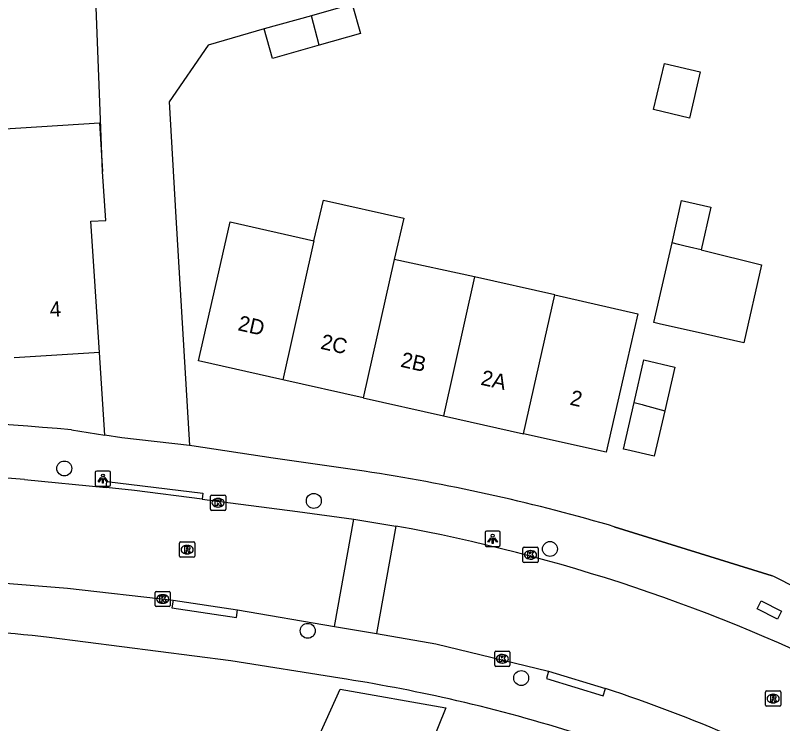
# Model space of a CAD drawing. Extents: x 163010 to 163853, y 382793 to 383982.
# Drawn here: x 163356.6 to 163406.8, y 383532.5 to 383579 of the extents above; entities that cross this region are included whole.
import ezdxf

# ---------------------------------------------------------------- set-up
doc = ezdxf.new("R2010")
doc.units = 0
for name, color, linetype in [('IMGEO_Boom', 7, 'Continuous'), ('IMGEO_Kolk', 7, 'Continuous'), ('IMGEO_Lichtpunt', 7, 'Continuous'), ('IMGEO_Muur', 7, 'Continuous'), ('IMGEO_Pand', 7, 'Continuous'), ('IMGEO_Pand_nummerreeks', 7, 'Continuous'), ('IMGEO_Rijbaan_lokaal_open', 7, 'Continuous'), ('IMGEO_Rioolput', 7, 'Continuous'), ('IMGEO_Voetpad_open', 7, 'Continuous')]:
    doc.layers.add(name, color=color, linetype=linetype)

msp = doc.modelspace()

# ---------------------------------------------------------------- linework, layer by layer
at = {"layer": 'IMGEO_Boom'}
for centre in [(163359.769, 383549.261), (163376.115, 383547.135), (163391.582, 383543.984), (163375.715, 383538.619), (163389.697, 383535.523)]:
    msp.add_circle(centre, 0.489, dxfattribs=at)
at = {"layer": 'IMGEO_Kolk'}
for p, q in [((163369.342, 383546.587), (163369.342, 383547.439)), ((163369.417, 383547.513), (163370.269, 383547.513)), ((163369.83, 383547.293), (163369.855, 383547.293)), ((163370.343, 383547.439), (163370.343, 383546.587)), ((163369.853, 383546.733), (163369.828, 383546.733)), ((163370.269, 383546.513), (163369.417, 383546.513)), ((163389.807, 383543.17), (163389.807, 383544.022)), ((163389.882, 383544.096), (163390.734, 383544.096)), ((163390.295, 383543.876), (163390.32, 383543.876)), ((163390.808, 383544.022), (163390.808, 383543.17)), ((163390.318, 383543.316), (163390.293, 383543.316)), ((163390.734, 383543.096), (163389.882, 383543.096)), ((163365.789, 383541.204), (163366.641, 383541.204)), ((163365.714, 383540.278), (163365.714, 383541.13)), ((163366.202, 383540.984), (163366.227, 383540.984)), ((163366.715, 383541.13), (163366.715, 383540.278)), ((163366.641, 383540.204), (163365.789, 383540.204)), ((163366.225, 383540.424), (163366.2, 383540.424)), ((163387.963, 383536.359), (163387.963, 383537.211)), ((163388.038, 383537.285), (163388.89, 383537.285)), ((163388.964, 383537.211), (163388.964, 383536.359)), ((163388.451, 383537.065), (163388.476, 383537.065)), ((163388.89, 383536.285), (163388.038, 383536.285)), ((163388.474, 383536.505), (163388.449, 383536.505))]:
    msp.add_line(p, q, dxfattribs=at)
for points in [[(163369.342, 383546.587), (163369.342, 383547.439)], [(163369.417, 383547.513), (163370.269, 383547.513)], [(163370.343, 383547.439), (163370.343, 383546.587)], [(163369.663, 383547.213), (163369.786, 383547.213), (163369.786, 383547.062), (163369.916, 383547.213), (163370.08, 383547.213), (163369.934, 383547.062), (163370.087, 383546.813), (163369.935, 383546.813), (163369.85, 383546.977), (163369.786, 383546.91), (163369.786, 383546.813), (163369.663, 383546.813), (163369.663, 383547.213)], [(163370.269, 383546.513), (163369.417, 383546.513)], [(163389.807, 383543.17), (163389.807, 383544.022)], [(163389.882, 383544.096), (163390.734, 383544.096)], [(163390.128, 383543.796), (163390.251, 383543.796), (163390.251, 383543.645), (163390.381, 383543.796), (163390.545, 383543.796), (163390.399, 383543.645), (163390.552, 383543.396), (163390.4, 383543.396), (163390.315, 383543.56), (163390.251, 383543.493), (163390.251, 383543.396), (163390.128, 383543.396), (163390.128, 383543.796)], [(163390.808, 383544.022), (163390.808, 383543.17)], [(163390.734, 383543.096), (163389.882, 383543.096)], [(163365.789, 383541.204), (163366.641, 383541.204)], [(163365.714, 383540.278), (163365.714, 383541.13)], [(163366.035, 383540.904), (163366.158, 383540.904), (163366.158, 383540.753), (163366.288, 383540.904), (163366.452, 383540.904), (163366.306, 383540.753), (163366.459, 383540.504), (163366.307, 383540.504), (163366.222, 383540.668), (163366.158, 383540.601), (163366.158, 383540.504), (163366.035, 383540.504), (163366.035, 383540.904)], [(163366.715, 383541.13), (163366.715, 383540.278)], [(163366.641, 383540.204), (163365.789, 383540.204)], [(163387.963, 383536.359), (163387.963, 383537.211)], [(163388.038, 383537.285), (163388.89, 383537.285)], [(163388.964, 383537.211), (163388.964, 383536.359)], [(163388.284, 383536.985), (163388.407, 383536.985), (163388.407, 383536.834), (163388.537, 383536.985), (163388.701, 383536.985), (163388.555, 383536.834), (163388.708, 383536.585), (163388.556, 383536.585), (163388.471, 383536.749), (163388.407, 383536.682), (163388.407, 383536.585), (163388.284, 383536.585), (163388.284, 383536.985)], [(163388.89, 383536.285), (163388.038, 383536.285)]]:
    msp.add_lwpolyline(points, dxfattribs=at)
for centre, start, end in [((163369.419, 383547.437), 91.552, 178.448), ((163369.419, 383547.437), 91.552, 178.448), ((163370.267, 383547.437), 1.552, 88.448), ((163370.267, 383547.437), 1.552, 88.448), ((163369.419, 383546.589), 181.552, 268.448), ((163369.419, 383546.589), 181.552, 268.448), ((163370.267, 383546.589), 271.552, 358.448), ((163370.267, 383546.589), 271.552, 358.448), ((163389.884, 383544.02), 91.552, 178.448), ((163389.884, 383544.02), 91.552, 178.448), ((163390.732, 383544.02), 1.552, 88.448), ((163390.732, 383544.02), 1.552, 88.448), ((163389.884, 383543.172), 181.552, 268.448), ((163389.884, 383543.172), 181.552, 268.448), ((163390.732, 383543.172), 271.552, 358.448), ((163390.732, 383543.172), 271.552, 358.448), ((163365.791, 383541.128), 91.552, 178.448), ((163365.791, 383541.128), 91.552, 178.448), ((163366.639, 383541.128), 1.552, 88.448), ((163366.639, 383541.128), 1.552, 88.448), ((163365.791, 383540.28), 181.552, 268.448), ((163365.791, 383540.28), 181.552, 268.448), ((163366.639, 383540.28), 271.552, 358.448), ((163366.639, 383540.28), 271.552, 358.448), ((163388.04, 383537.209), 91.552, 178.448), ((163388.04, 383537.209), 91.552, 178.448), ((163388.888, 383537.209), 1.552, 88.448), ((163388.888, 383537.209), 1.552, 88.448), ((163388.04, 383536.361), 181.552, 268.448), ((163388.04, 383536.361), 181.552, 268.448), ((163388.888, 383536.361), 271.552, 358.448), ((163388.888, 383536.361), 271.552, 358.448)]:
    msp.add_arc(centre, 0.0765, start, end, dxfattribs=at)
for centre, major_axis, ratio, start_param, end_param in [((163369.829, 383547.013), (-0.387, 0.002), 0.722429, 4.712389, 7.853982), ((163369.854, 383547.013), (-0.39, 0.002), 0.717154, 1.570796, 4.712389), ((163390.294, 383543.596), (-0.387, 0.002), 0.722429, 4.712389, 7.853982), ((163390.319, 383543.596), (-0.39, 0.002), 0.717154, 1.570796, 4.712389), ((163366.201, 383540.704), (-0.387, 0.002), 0.722429, 4.712389, 7.853982), ((163366.226, 383540.704), (-0.39, 0.002), 0.717154, 1.570796, 4.712389), ((163388.45, 383536.785), (-0.387, 0.002), 0.722429, 4.712389, 7.853982), ((163388.475, 383536.785), (-0.39, 0.002), 0.717154, 1.570796, 4.712389)]:
    msp.add_ellipse(centre, major_axis=major_axis, ratio=ratio, start_param=start_param, end_param=end_param, dxfattribs=at)
at = {"layer": 'IMGEO_Lichtpunt'}
for p, q in [((163361.797, 383548.997), (163361.797, 383548.19)), ((163361.797, 383548.997), (163361.797, 383548.19)), ((163362.699, 383549.092), (163361.891, 383549.092)), ((163362.699, 383549.092), (163361.891, 383549.092)), ((163362.793, 383548.19), (163362.793, 383548.997)), ((163362.793, 383548.19), (163362.793, 383548.997)), ((163361.891, 383548.096), (163362.699, 383548.096)), ((163361.891, 383548.096), (163362.699, 383548.096)), ((163387.329, 383545.057), (163387.329, 383544.25)), ((163387.329, 383545.057), (163387.329, 383544.25)), ((163388.231, 383545.152), (163387.423, 383545.152)), ((163388.231, 383545.152), (163387.423, 383545.152)), ((163388.325, 383544.25), (163388.325, 383545.057)), ((163388.325, 383544.25), (163388.325, 383545.057)), ((163387.423, 383544.156), (163388.231, 383544.156)), ((163387.423, 383544.156), (163388.231, 383544.156))]:
    msp.add_line(p, q, dxfattribs=at)
for points in [[(163362.171, 383548.661), (163362.21, 383548.633), (163362.022, 383548.371), (163361.984, 383548.398), (163362.171, 383548.661)], [(163362.273, 383548.613), (163362.32, 383548.613), (163362.32, 383548.291), (163362.273, 383548.291), (163362.273, 383548.613)], [(163362.383, 383548.633), (163362.421, 383548.66), (163362.608, 383548.398), (163362.569, 383548.37), (163362.383, 383548.633)], [(163387.703, 383544.721), (163387.742, 383544.693), (163387.554, 383544.431), (163387.516, 383544.458), (163387.703, 383544.721)], [(163387.915, 383544.693), (163387.953, 383544.72), (163388.14, 383544.458), (163388.101, 383544.43), (163387.915, 383544.693)], [(163387.805, 383544.673), (163387.852, 383544.673), (163387.852, 383544.351), (163387.805, 383544.351), (163387.805, 383544.673)]]:
    msp.add_lwpolyline(points, dxfattribs=at)
for centre in [(163362.296, 383548.795), (163387.828, 383544.855)]:
    msp.add_circle(centre, 0.0994, dxfattribs=at)
for centre, start, end in [((163361.891, 383548.997), 90, 180), ((163361.891, 383548.997), 90, 180), ((163362.699, 383548.997), 0, 90), ((163362.699, 383548.997), 0, 90), ((163361.891, 383548.19), 180, 270), ((163361.891, 383548.19), 180, 270), ((163362.699, 383548.19), 270, 0), ((163362.699, 383548.19), 270, 360), ((163387.423, 383545.057), 90, 180), ((163387.423, 383545.057), 90, 180), ((163388.231, 383545.057), 0, 90), ((163388.231, 383545.057), 0, 90), ((163387.423, 383544.25), 180, 270), ((163387.423, 383544.25), 180, 270), ((163388.231, 383544.25), 270, 0), ((163388.231, 383544.25), 270, 360)]:
    msp.add_arc(centre, 0.0946, start, end, dxfattribs=at)
at = {"layer": 'IMGEO_Muur'}
for points in [[(163372.861, 383578.068), (163369.203, 383577.01), (163366.63, 383573.299), (163367.086, 383565.73)], [(163395.787, 383545.442), (163406.135, 383542.223)]]:
    msp.add_lwpolyline(points, dxfattribs=at)
msp.add_arc((163361.756, 383431.525), 105.221, 68.21207, 77.24489, dxfattribs=at)
at = {"layer": 'IMGEO_Pand'}
for points in [[(163378.623, 383579.69), (163375.955, 383578.939)], [(163378.623, 383579.69), (163379.165, 383577.765), (163376.463, 383577.004)], [(163375.955, 383578.939), (163372.861, 383578.068)], [(163376.463, 383577.004), (163375.955, 383578.939)], [(163376.463, 383577.004), (163373.403, 383576.143), (163372.861, 383578.068)], [(163401.431, 383575.26), (163400.714, 383572.214), (163398.375, 383572.796), (163399.086, 383575.813), (163401.431, 383575.26)], [(163355.937, 383565.104), (163355.731, 383568.306), (163355.525, 383571.498), (163362.076, 383571.92), (163362.282, 383568.728)], [(163362.071, 383556.869), (163361.75, 383561.858), (163361.518, 383565.463), (163362.488, 383565.525), (163362.282, 383568.728)], [(163376.123, 383564.187), (163376.742, 383566.842), (163382.002, 383565.667), (163381.378, 383562.96)], [(163399.578, 383564.052), (163400.204, 383566.823), (163402.118, 383566.391), (163401.486, 383563.585)], [(163374.079, 383555.076), (163368.557, 383556.316), (163369.667, 383561.192), (163370.63, 383565.425), (163376.123, 383564.187)], [(163376.123, 383564.187), (163374.079, 383555.076)], [(163401.486, 383563.585), (163401.655, 383563.543), (163405.438, 383562.602), (163404.284, 383557.493), (163401.092, 383558.213), (163398.826, 383558.724), (163398.397, 383558.821), (163399.578, 383564.052)], [(163401.486, 383563.585), (163400.728, 383563.774), (163400.448, 383563.843), (163400.006, 383563.949), (163399.578, 383564.052)], [(163381.378, 383562.96), (163379.348, 383553.893)], [(163386.645, 383561.815), (163381.378, 383562.96)], [(163386.645, 383561.815), (163384.608, 383552.712)], [(163391.892, 383560.632), (163386.645, 383561.815)], [(163389.857, 383551.533), (163391.892, 383560.632)], [(163391.892, 383560.632), (163397.329, 383559.406), (163396.367, 383555.196), (163395.254, 383550.321), (163389.857, 383551.533)], [(163362.071, 383556.869), (163356.489, 383556.51)], [(163397.095, 383553.585), (163397.734, 383556.372), (163399.761, 383555.907), (163399.103, 383553.043)], [(163379.348, 383553.893), (163374.079, 383555.076)], [(163379.348, 383553.893), (163384.608, 383552.712)], [(163399.103, 383553.043), (163398.418, 383550.063), (163396.617, 383550.477), (163396.395, 383550.528), (163397.095, 383553.585)], [(163397.095, 383553.585), (163397.352, 383553.516), (163397.622, 383553.443), (163397.753, 383553.408), (163399.103, 383553.043)], [(163384.608, 383552.712), (163389.857, 383551.533)], [(163375.895, 383530.496), (163377.833, 383534.788), (163384.752, 383533.563), (163382.435, 383527.774), (163375.895, 383530.496)]]:
    msp.add_lwpolyline(points, dxfattribs=at)
at = {"layer": 'IMGEO_Rijbaan_lokaal_open'}
for points in [[(163362.282, 383568.728), (163361.794, 383581.206)], [(163372.861, 383578.068), (163369.203, 383577.01), (163366.63, 383573.299), (163367.086, 383565.73), (163367.981, 383550.763)], [(163362.42, 383551.44), (163362.071, 383556.869)], [(163367.981, 383550.763), (163363.531, 383551.261), (163362.42, 383551.44)], [(163357.158, 383548.536), (163362.502, 383548.004)], [(163368.792, 383547.248), (163364.37, 383547.818), (163362.502, 383548.004)], [(163368.792, 383547.248), (163375.035, 383546.444), (163378.74, 383545.94)], [(163377.463, 383538.905), (163378.74, 383545.94)], [(163378.74, 383545.94), (163381.493, 383545.489)], [(163381.493, 383545.489), (163380.213, 383538.433)], [(163341.214, 383542.459), (163348.833, 383542.316), (163359.981, 383541.417), (163366.895, 383540.628)], [(163366.895, 383540.628), (163371.116, 383539.995)], [(163371.116, 383539.995), (163377.463, 383538.905)], [(163377.463, 383538.905), (163380.213, 383538.433)], [(163380.213, 383538.433), (163384.105, 383537.765), (163391.492, 383535.979)], [(163391.492, 383535.979), (163395.217, 383534.84)]]:
    msp.add_lwpolyline(points, dxfattribs=at)
for centre, radius, start, end in [((163342.161, 383367.127), 182.028, 85.27403, 93.88768), ((163361.256, 383434.571), 112.749, 63.23255, 79.66022), ((163364.957, 383442.706), 96.976, 66.50318, 71.81796)]:
    msp.add_arc(centre, radius, start, end, dxfattribs=at)
at = {"layer": 'IMGEO_Rioolput'}
for p, q in [((163367.317, 383543.516), (163367.317, 383544.368)), ((163367.392, 383544.442), (163368.244, 383544.442)), ((163367.805, 383544.222), (163367.83, 383544.222)), ((163368.318, 383544.368), (163368.318, 383543.516)), ((163368.244, 383543.442), (163367.392, 383543.442)), ((163367.828, 383543.662), (163367.803, 383543.662)), ((163405.777, 383534.678), (163406.629, 383534.678)), ((163405.702, 383533.752), (163405.702, 383534.604)), ((163406.19, 383534.458), (163406.215, 383534.458)), ((163406.703, 383534.604), (163406.703, 383533.752)), ((163406.629, 383533.678), (163405.777, 383533.678)), ((163406.213, 383533.898), (163406.188, 383533.898))]:
    msp.add_line(p, q, dxfattribs=at)
for points in [[(163367.317, 383543.516), (163367.317, 383544.368)], [(163367.392, 383544.442), (163368.244, 383544.442)], [(163368.318, 383544.368), (163368.318, 383543.516)], [(163367.906, 383544.14), (163367.654, 383544.142), (163367.654, 383543.742)], [(163367.654, 383543.742), (163367.778, 383543.742), (163367.778, 383543.904), (163367.789, 383543.904)], [(163367.832, 383544.061), (163367.778, 383544.061), (163367.778, 383543.98)], [(163367.778, 383543.98), (163367.83, 383543.98)], [(163367.836, 383543.875), (163367.907, 383543.742), (163368.047, 383543.742), (163367.982, 383543.868)], [(163368.244, 383543.442), (163367.392, 383543.442)], [(163405.777, 383534.678), (163406.629, 383534.678)], [(163405.702, 383533.752), (163405.702, 383534.604)], [(163406.291, 383534.376), (163406.039, 383534.378), (163406.039, 383533.978)], [(163406.217, 383534.297), (163406.163, 383534.297), (163406.163, 383534.216)], [(163406.163, 383534.216), (163406.215, 383534.216)], [(163406.703, 383534.604), (163406.703, 383533.752)], [(163406.629, 383533.678), (163405.777, 383533.678)], [(163406.039, 383533.978), (163406.163, 383533.978), (163406.163, 383534.14), (163406.174, 383534.14)], [(163406.221, 383534.111), (163406.292, 383533.978), (163406.432, 383533.978), (163406.367, 383534.104)]]:
    msp.add_lwpolyline(points, dxfattribs=at)
for centre, radius, start, end in [((163367.394, 383544.366), 0.0765, 91.552, 178.448), ((163367.394, 383544.366), 0.0765, 91.552, 178.448), ((163368.242, 383544.366), 0.0765, 1.552, 88.448), ((163368.242, 383544.366), 0.0765, 1.552, 88.448), ((163367.788, 383543.851), 0.0533, 26.0293, 88.6989), ((163367.814, 383544.169), 0.19, 274.7715, 282.9687), ((163367.838, 383543.965), 0.0964, 77.0061, 93.1865), ((163367.852, 383544.022), 0.0378, 276.6634, 79.6772), ((163367.905, 383544.03), 0.109, 350.3612, 89.416), ((163367.903, 383544.03), 0.112, 277.5842, 350.9817), ((163367.887, 383543.815), 0.108, 29.5134, 73.7905), ((163367.394, 383543.518), 0.0765, 181.552, 268.448), ((163367.394, 383543.518), 0.0765, 181.552, 268.448), ((163368.242, 383543.518), 0.0765, 271.552, 358.448), ((163368.242, 383543.518), 0.0765, 271.552, 358.448), ((163405.779, 383534.602), 0.0765, 91.552, 178.448), ((163405.779, 383534.602), 0.0765, 91.552, 178.448), ((163406.627, 383534.602), 0.0765, 1.552, 88.448), ((163406.627, 383534.602), 0.0765, 1.552, 88.448), ((163406.199, 383534.405), 0.19, 274.7715, 282.9687), ((163406.223, 383534.201), 0.0964, 77.0061, 93.1865), ((163406.237, 383534.258), 0.0378, 276.6634, 79.6772), ((163406.29, 383534.266), 0.109, 350.3612, 89.416), ((163406.288, 383534.266), 0.112, 277.5842, 350.9817), ((163406.272, 383534.051), 0.108, 29.5134, 73.7905), ((163405.779, 383533.754), 0.0765, 181.552, 268.448), ((163405.779, 383533.754), 0.0765, 181.552, 268.448), ((163406.173, 383534.087), 0.0533, 26.0293, 88.6989), ((163406.627, 383533.754), 0.0765, 271.552, 358.448), ((163406.627, 383533.754), 0.0765, 271.552, 358.448)]:
    msp.add_arc(centre, radius, start, end, dxfattribs=at)
for centre, major_axis, ratio, start_param, end_param in [((163367.804, 383543.942), (-0.387, 0.002), 0.722429, 4.712389, 7.853982), ((163367.829, 383543.942), (-0.39, 0.002), 0.717154, 1.570796, 4.712389), ((163406.189, 383534.178), (-0.387, 0.002), 0.722429, 4.712389, 7.853982), ((163406.214, 383534.178), (-0.39, 0.002), 0.717154, 1.570796, 4.712389)]:
    msp.add_ellipse(centre, major_axis=major_axis, ratio=ratio, start_param=start_param, end_param=end_param, dxfattribs=at)
at = {"layer": 'IMGEO_Voetpad_open'}
for points in [[(163360.245, 383551.79), (163362.42, 383551.44)], [(163379.409, 383549.079), (163373.451, 383549.934), (163368.116, 383550.748), (163367.981, 383550.763)], [(163362.502, 383548.004), (163362.55, 383548.41), (163368.84, 383547.65), (163368.792, 383547.248)], [(163417.063, 383536.698), (163406.25, 383542.187), (163406.135, 383542.223), (163395.787, 383545.442), (163395.42, 383545.556)], [(163366.895, 383540.628), (163366.823, 383540.134), (163371.044, 383539.501), (163371.116, 383539.995)], [(163405.419, 383540.59), (163406.756, 383539.911), (163406.485, 383539.376), (163405.147, 383540.055), (163405.419, 383540.59)], [(163377.81, 383535.516), (163370.681, 383536.653), (163358.786, 383538.189)], [(163391.492, 383535.979), (163391.347, 383535.502), (163395.072, 383534.362), (163395.217, 383534.84)]]:
    msp.add_lwpolyline(points, dxfattribs=at)
for centre, radius, start, end in [((163342.233, 383355.387), 197.227, 84.76017, 93.64141), ((163360.577, 383425.351), 125.153, 73.83527, 81.34593), ((163344.17, 383405.903), 133.091, 83.69518, 91.43898), ((163361.621, 383430.922), 105.839, 77.24589, 81.20166), ((163361.756, 383431.525), 105.221, 68.21207, 77.24489)]:
    msp.add_arc(centre, radius, start, end, dxfattribs=at)

# ---------------------------------------------------------------- texts
at = {"layer": 'IMGEO_Pand_nummerreeks'}
for s, rotation, p in [('4', 3.6784, (163358.843, 383559.188)), ('2D', 347.3438, (163371.086, 383558.33)), ('2C', 347.3438, (163376.506, 383557.114)), ('2B', 347.3434, (163381.745, 383555.937)), ('2A', 347.3434, (163386.999, 383554.757)), ('2', 347.3438, (163392.837, 383553.447))]:
    msp.add_text(s, height=1, rotation=rotation, dxfattribs=at).set_placement(p)

doc.saveas('drawing.dxf')
